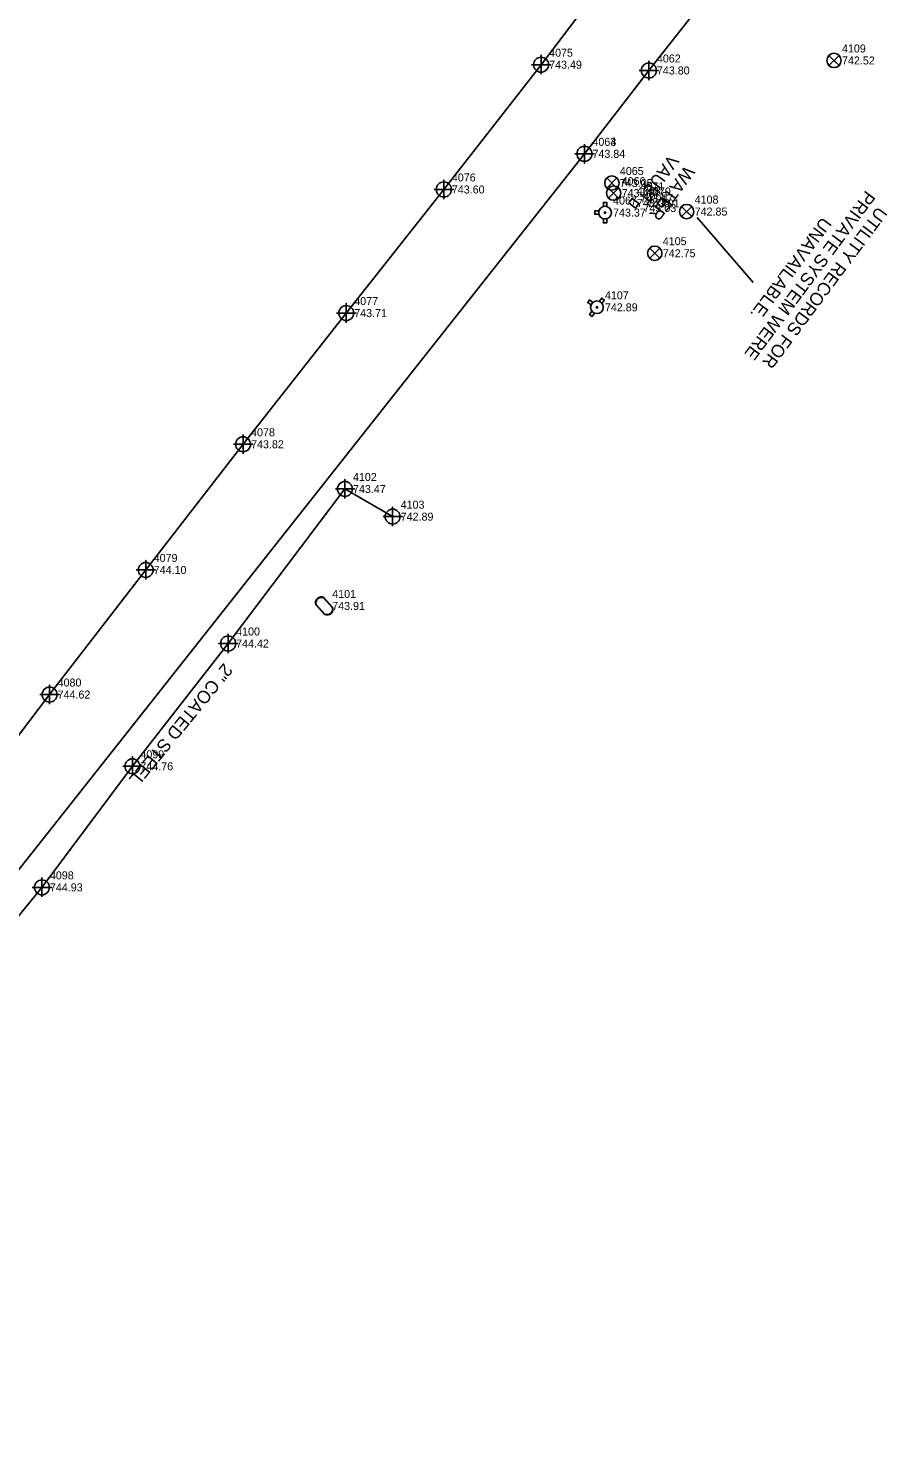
# Model space of a CAD drawing. Extents: x 1622486 to 1624761, y 758733 to 760816.
# Drawn here: x 1622789.3 to 1623059.1, y 758736.4 to 759180.5 of the extents above; entities that cross this region are included whole.
import ezdxf

# ---------------------------------------------------------------- set-up
doc = ezdxf.new("R2010")
doc.units = 0
for name, color, linetype in [('Exist Structure Minor Pipes HDPE 15 Inch', 7, 'Continuous'), ('Exist Structure Minor Pipes RCP 15 Inch Invert', 7, 'Continuous'), ('Exist Structure Minor Pipes RCP 30 Inch Text', 7, 'Continuous'), ('Exist Utilities Gas UG Line SUE', 7, 'Continuous'), ('Exist Utilities Gas UG Line SUE Cogo Elevation', 7, 'Continuous'), ('Exist Utilities Gas UG Line SUE Cogo Number', 7, 'Continuous'), ('Exist Utilities Gas UG Line SUE Cogo Point CELL', 7, 'Continuous'), ('Exist Utilities Water Fire Hydrant CELL', 7, 'Continuous'), ('Exist Utilities Water Fire Hydrant Cogo Elevation', 7, 'Continuous'), ('Exist Utilities Water Fire Hydrant Cogo Number', 7, 'Continuous'), ('Exist Utilities Water Meter CELL', 7, 'Continuous'), ('Exist Utilities Water Meter Cogo Elevation', 7, 'Continuous'), ('Exist Utilities Water Meter Cogo Number', 7, 'Continuous'), ('Exist Utilities Water UG Line', 7, 'Continuous'), ('Exist Utilities Water UG Line Cogo Elevation', 7, 'Continuous'), ('Exist Utilities Water UG Line Cogo Number', 7, 'Continuous'), ('Exist Utilities Water UG Line SUE', 7, 'Continuous'), ('Exist Utilities Water UG Line SUE Cogo Elevation', 7, 'Continuous'), ('Exist Utilities Water UG Line SUE Cogo Number', 7, 'Continuous'), ('Exist Utilities Water UG Line SUE Cogo Point CELL', 7, 'Continuous'), ('Exist Utilities Water Valve CELL', 7, 'Continuous'), ('Exist Utilities Water Valve Cogo Elevation', 7, 'Continuous'), ('Exist Utilities Water Valve Cogo Number', 7, 'Continuous')]:
    doc.layers.add(name, color=color, linetype=linetype)

msp = doc.modelspace()

# ---------------------------------------------------------------- linework, layer by layer
at = {"layer": 'Exist Structure Minor Pipes HDPE 15 Inch'}
msp.add_lwpolyline([(1622998.13, 759121.44), (1623015.65, 759101.17)], dxfattribs=at)
at = {"layer": 'Exist Utilities Gas UG Line SUE'}
for points in [[(1622980.39, 759210.11), (1622949.39, 759169.17), (1622919.02, 759130.2), (1622888.55, 759091.6), (1622856.34, 759050.62), (1622825.93, 759011.37), (1622795.93, 758972.46), (1622767.05, 758934.51), (1622738.7, 758897.61), (1622711.11, 758861.1), (1622683.5, 758824.4), (1622654.21, 758786.19), (1622629.8, 758753.56)], [(1622903.04, 759028.02), (1622888.15, 759036.66), (1622851.67, 758988.4), (1622821.78, 758950.05), (1622793.53, 758912.24), (1622765.71, 758878.28), (1622740.85, 758848.28), (1622735.92, 758843.17), (1622706.21, 758806.37), (1622676.37, 758768.27), (1622651.59, 758736.35)]]:
    msp.add_lwpolyline(points, dxfattribs=at)
at = {"layer": 'Exist Utilities Gas UG Line SUE Cogo Point CELL'}
for points in [[(1622946.39, 759169.17), (1622952.39, 759169.17), (1622949.39, 759169.17), (1622949.39, 759172.17), (1622949.39, 759166.17)], [(1622916.02, 759130.2), (1622922.02, 759130.2), (1622919.02, 759130.2), (1622919.02, 759133.2), (1622919.02, 759127.2)], [(1622885.55, 759091.6), (1622891.55, 759091.6), (1622888.55, 759091.6), (1622888.55, 759094.6), (1622888.55, 759088.6)], [(1622853.34, 759050.62), (1622859.34, 759050.62), (1622856.34, 759050.62), (1622856.34, 759053.62), (1622856.34, 759047.62)], [(1622885.15, 759036.66), (1622891.15, 759036.66), (1622888.15, 759036.66), (1622888.15, 759039.66), (1622888.15, 759033.66)], [(1622900.04, 759028.02), (1622906.04, 759028.02), (1622903.04, 759028.02), (1622903.04, 759031.02), (1622903.04, 759025.02)], [(1622822.93, 759011.37), (1622828.93, 759011.37), (1622825.93, 759011.37), (1622825.93, 759014.37), (1622825.93, 759008.37)], [(1622848.67, 758988.4), (1622854.67, 758988.4), (1622851.67, 758988.4), (1622851.67, 758991.4), (1622851.67, 758985.4)], [(1622792.93, 758972.46), (1622798.93, 758972.46), (1622795.93, 758972.46), (1622795.93, 758975.46), (1622795.93, 758969.46)], [(1622818.78, 758950.05), (1622824.78, 758950.05), (1622821.78, 758950.05), (1622821.78, 758953.05), (1622821.78, 758947.05)], [(1622790.53, 758912.24), (1622796.53, 758912.24), (1622793.53, 758912.24), (1622793.53, 758915.24), (1622793.53, 758909.24)]]:
    msp.add_lwpolyline(points, dxfattribs=at)
for centre in [(1622949.39, 759169.17), (1622919.02, 759130.2), (1622888.55, 759091.6), (1622856.34, 759050.62), (1622888.15, 759036.66), (1622903.04, 759028.02), (1622825.93, 759011.37), (1622851.67, 758988.4), (1622795.93, 758972.46), (1622821.78, 758950.05), (1622793.53, 758912.24)]:
    msp.add_circle(centre, 2.34, dxfattribs=at)
at = {"layer": 'Exist Utilities Water Fire Hydrant CELL'}
for p, q in [((1622969.36, 759122.98), (1622969.36, 759122.98)), ((1622966.81, 759093.4), (1622966.81, 759093.4))]:
    msp.add_line(p, q, dxfattribs=at)
for points in [[(1622967.45, 759123.49), (1622966.16, 759123.49), (1622966.16, 759122.46), (1622967.45, 759122.46)], [(1622968.85, 759124.89), (1622968.85, 759126.18), (1622969.88, 759126.18), (1622969.88, 759124.86)], [(1622968.85, 759121.06), (1622968.85, 759119.78), (1622969.88, 759119.78), (1622969.88, 759121.09)], [(1622965.58, 759094.95), (1622964.55, 759095.72), (1622963.94, 759094.89), (1622964.97, 759094.13)], [(1622967.54, 759095.24), (1622968.31, 759096.28), (1622969.13, 759095.66), (1622968.35, 759094.61)], [(1622965.26, 759092.17), (1622964.5, 759091.13), (1622965.32, 759090.52), (1622966.1, 759091.58)]]:
    msp.add_lwpolyline(points, dxfattribs=at)
for centre, radius in [((1622969.36, 759122.98), 1.98), ((1622969.36, 759122.98), 0.243), ((1622966.81, 759093.4), 1.98), ((1622966.81, 759093.4), 0.243)]:
    msp.add_circle(centre, radius, dxfattribs=at)
at = {"layer": 'Exist Utilities Water Meter CELL'}
msp.add_line((1622881.67, 759000.13), (1622881.67, 759000.13), dxfattribs=at)
for points in [[(1622881.79, 758997.48), (1622879.03, 759000.51)], [(1622881.89, 758997.57), (1622879.13, 759000.6)], [(1622881.46, 759002.69), (1622884.2, 758999.67)], [(1622881.56, 759002.78), (1622884.3, 758999.77)]]:
    msp.add_lwpolyline(points, dxfattribs=at)
for centre, radius, start, end in [((1622880.79, 759001.09), 1.86, 65.4819, 198.2832), ((1622880.8, 759001.08), 1.73, 67.6048, 196.0862), ((1622882.54, 758999.17), 1.86, 245.9522, 18.6122), ((1622882.55, 758999.16), 1.73, 247.431, 17.1767)]:
    msp.add_arc(centre, radius, start, end, dxfattribs=at)
at = {"layer": 'Exist Utilities Water UG Line'}
for points in [[(1622962.92, 759141.34), (1622644.34, 758738.28)], [(1622976.79, 759126.01), (1622978.86, 759124.41), (1622979.92, 759125.83), (1622977.87, 759127.39), (1622976.79, 759126.01)]]:
    msp.add_lwpolyline(points, dxfattribs=at)
at = {"layer": 'Exist Utilities Water UG Line SUE'}
msp.add_lwpolyline([(1622962.92, 759141.34), (1622983.04, 759167.36), (1623019.05, 759213.17), (1623085.24, 759299.23), (1623127.12, 759352.96), (1623168.6, 759407.5), (1623192.9, 759438.13), (1623227.86, 759483.32), (1623280.43, 759553.63), (1623319.36, 759606.3), (1623348.28, 759642.26)], dxfattribs=at)
at = {"layer": 'Exist Utilities Water UG Line SUE Cogo Point CELL'}
for points in [[(1622983.04, 759170.36), (1622983.04, 759164.36), (1622983.04, 759167.36), (1622986.04, 759167.36), (1622980.04, 759167.36)], [(1622962.92, 759144.34), (1622962.92, 759138.34), (1622962.92, 759141.34), (1622965.92, 759141.34), (1622959.92, 759141.34)], [(1622962.92, 759144.33), (1622962.92, 759138.33), (1622962.92, 759141.33), (1622965.92, 759141.33), (1622959.92, 759141.33)]]:
    msp.add_lwpolyline(points, dxfattribs=at)
for centre in [(1622983.04, 759167.36), (1622962.92, 759141.33), (1622962.92, 759141.34)]:
    msp.add_circle(centre, 2.34, dxfattribs=at)
at = {"layer": 'Exist Utilities Water Valve CELL'}
for points in [[(1623042.4, 759172.06), (1623039.25, 759168.91), (1623040.83, 759170.49), (1623042.4, 759168.91), (1623039.25, 759172.06)], [(1622973.06, 759133.79), (1622969.91, 759130.64), (1622971.48, 759132.22), (1622973.06, 759130.64), (1622969.91, 759133.79)], [(1622973.6, 759130.65), (1622970.45, 759127.5), (1622972.03, 759129.07), (1622973.6, 759127.5), (1622970.45, 759130.65)], [(1622996.4, 759124.87), (1622993.25, 759121.72), (1622994.83, 759123.3), (1622996.4, 759121.72), (1622993.25, 759124.87)], [(1622986.45, 759111.86), (1622983.3, 759108.71), (1622984.88, 759110.29), (1622986.45, 759108.71), (1622983.3, 759111.86)]]:
    msp.add_lwpolyline(points, dxfattribs=at)
for centre in [(1623040.83, 759170.49), (1622971.48, 759132.22), (1622972.03, 759129.07), (1622994.83, 759123.3), (1622984.88, 759110.29)]:
    msp.add_circle(centre, 2.23, dxfattribs=at)

# ---------------------------------------------------------------- texts
at = {"layer": 'Exist Structure Minor Pipes RCP 15 Inch Invert'}
for s, p in [('VAULT', (1622989.52, 759141.38)), ('WATER', (1622994.43, 759137.92)), ('PRIVATE SYSTEM WERE', (1623050.79, 759130.14)), ('UTILITY RECORDS FOR', (1623054.52, 759125.1)), ('UNAVAILABLE.', (1623037.15, 759121.85))]:
    msp.add_text(s, height=4, rotation=233.3735, dxfattribs=at).set_placement(p)
at = {"layer": 'Exist Structure Minor Pipes RCP 30 Inch Text'}
msp.add_text('2" COATED STEEL', height=4, rotation=230.6687, dxfattribs=at).set_placement((1622850.34, 758982.51))
at = {"layer": 'Exist Utilities Gas UG Line SUE Cogo Elevation'}
for s, p in [('743.49', (1622951.89, 759167.92)), ('743.60', (1622921.52, 759128.95)), ('743.71', (1622891.05, 759090.35)), ('743.82', (1622858.84, 759049.37)), ('743.47', (1622890.65, 759035.41)), ('742.89', (1622905.54, 759026.77)), ('744.10', (1622828.43, 759010.12)), ('744.42', (1622854.17, 758987.15)), ('744.62', (1622798.43, 758971.21)), ('744.76', (1622824.28, 758948.8)), ('744.93', (1622796.03, 758910.99))]:
    msp.add_text(s, height=2.5, dxfattribs=at).set_placement(p)
at = {"layer": 'Exist Utilities Gas UG Line SUE Cogo Number'}
for s, p in [('4075', (1622951.89, 759171.67)), ('4076', (1622921.52, 759132.7)), ('4077', (1622891.05, 759094.1)), ('4078', (1622858.84, 759053.12)), ('4102', (1622890.65, 759039.16)), ('4103', (1622905.54, 759030.52)), ('4079', (1622828.43, 759013.87)), ('4100', (1622854.17, 758990.9)), ('4080', (1622798.43, 758974.96)), ('4099', (1622824.28, 758952.55)), ('4098', (1622796.03, 758914.74))]:
    msp.add_text(s, height=2.5, dxfattribs=at).set_placement(p)
at = {"layer": 'Exist Utilities Water Fire Hydrant Cogo Elevation'}
for s, p in [('743.37', (1622971.86, 759121.73)), ('742.89', (1622969.31, 759092.15))]:
    msp.add_text(s, height=2.5, dxfattribs=at).set_placement(p)
at = {"layer": 'Exist Utilities Water Fire Hydrant Cogo Number'}
for s, p in [('4067', (1622971.86, 759125.48)), ('4107', (1622969.31, 759095.9))]:
    msp.add_text(s, height=2.5, dxfattribs=at).set_placement(p)
at = {"layer": 'Exist Utilities Water Meter Cogo Elevation'}
msp.add_text('743.91', height=2.5, dxfattribs=at).set_placement((1622884.17, 758998.88))
at = {"layer": 'Exist Utilities Water Meter Cogo Number'}
msp.add_text('4101', height=2.5, dxfattribs=at).set_placement((1622884.17, 759002.63))
at = {"layer": 'Exist Utilities Water UG Line Cogo Elevation'}
for s, p in [('743.17', (1622980.37, 759126.14)), ('743.08', (1622979.29, 759124.76)), ('743.03', (1622981.36, 759123.16)), ('743.01', (1622982.42, 759124.58))]:
    msp.add_text(s, height=2.5, dxfattribs=at).set_placement(p)
at = {"layer": 'Exist Utilities Water UG Line Cogo Number'}
for s, p in [('4071', (1622980.37, 759129.89)), ('4068', (1622979.29, 759128.51)), ('4069', (1622981.36, 759126.91)), ('4070', (1622982.42, 759128.33))]:
    msp.add_text(s, height=2.5, dxfattribs=at).set_placement(p)
at = {"layer": 'Exist Utilities Water UG Line SUE Cogo Elevation'}
for s, p in [('743.80', (1622985.54, 759166.11)), ('743.84', (1622965.42, 759140.08)), ('743.84', (1622965.42, 759140.09))]:
    msp.add_text(s, height=2.5, dxfattribs=at).set_placement(p)
at = {"layer": 'Exist Utilities Water UG Line SUE Cogo Number'}
for s, p in [('4062', (1622985.54, 759169.86)), ('4064', (1622965.42, 759143.83)), ('4063', (1622965.42, 759143.84))]:
    msp.add_text(s, height=2.5, dxfattribs=at).set_placement(p)
at = {"layer": 'Exist Utilities Water Valve Cogo Elevation'}
for s, p in [('742.52', (1623043.33, 759169.24)), ('743.05', (1622973.98, 759130.97)), ('743.48', (1622974.53, 759127.82)), ('742.85', (1622997.33, 759122.05)), ('742.75', (1622987.38, 759109.04))]:
    msp.add_text(s, height=2.5, dxfattribs=at).set_placement(p)
at = {"layer": 'Exist Utilities Water Valve Cogo Number'}
for s, p in [('4109', (1623043.33, 759172.99)), ('4065', (1622973.98, 759134.72)), ('4066', (1622974.53, 759131.57)), ('4108', (1622997.33, 759125.8)), ('4105', (1622987.38, 759112.79))]:
    msp.add_text(s, height=2.5, dxfattribs=at).set_placement(p)

doc.saveas('drawing.dxf')
